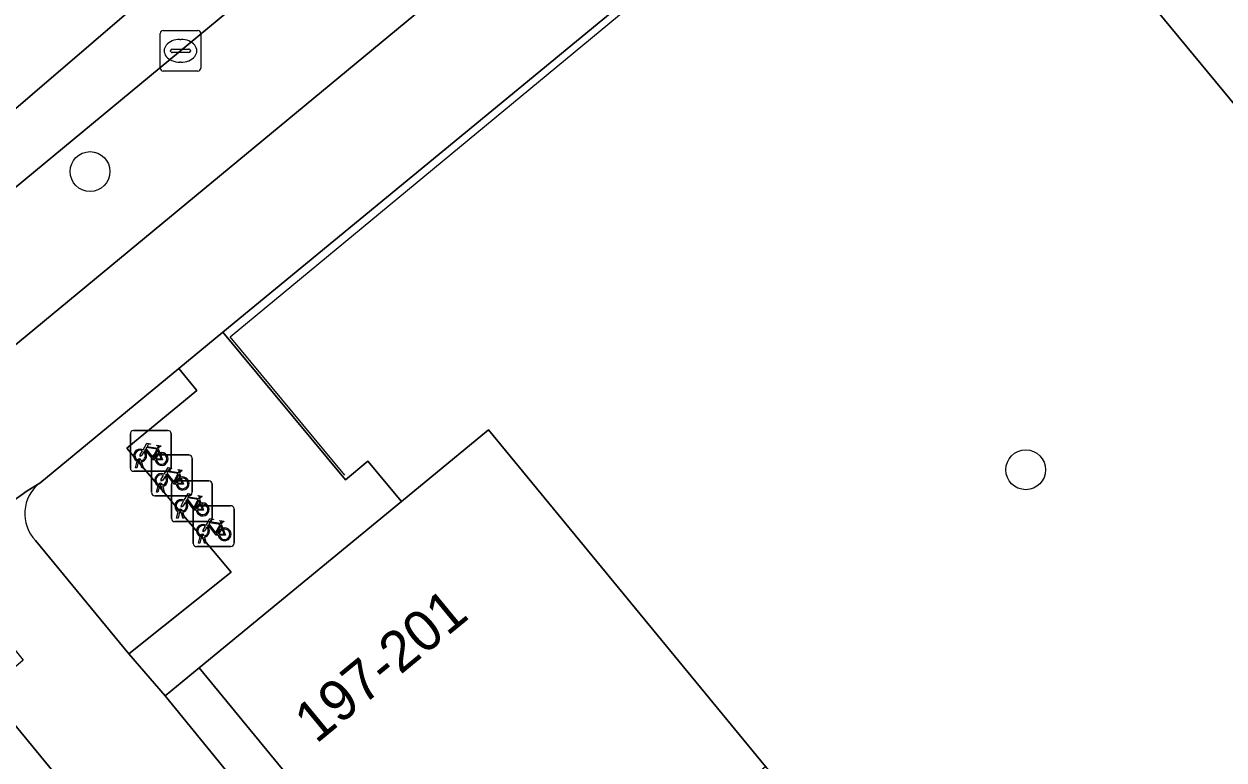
# Model space of a CAD drawing. Extents: x 162344 to 162869, y 381217 to 381818.
# Drawn here: x 162429.6 to 162459.05, y 381714.88 to 381732.95 of the extents above; entities that cross this region are included whole.
import ezdxf

# ---------------------------------------------------------------- set-up
doc = ezdxf.new("R2010")
doc.units = 0
for name, color, linetype in [('IMGEO_Berm_groen', 7, 'Continuous'), ('IMGEO_Boom', 7, 'Continuous'), ('IMGEO_Fietsenrek', 7, 'Continuous'), ('IMGEO_Fietspad_open', 7, 'Continuous'), ('IMGEO_Groenvoorziening', 7, 'Continuous'), ('IMGEO_Hek', 7, 'Continuous'), ('IMGEO_Kolk', 7, 'Continuous'), ('IMGEO_Pand', 7, 'Continuous'), ('IMGEO_Pand_nummerreeks', 7, 'Continuous'), ('IMGEO_Parkeervlak_open', 7, 'Continuous'), ('IMGEO_Rijbaan_lokaal_open', 7, 'Continuous'), ('IMGEO_Voetpad_open', 7, 'Continuous')]:
    doc.layers.add(name, color=color, linetype=linetype)

msp = doc.modelspace()

# ---------------------------------------------------------------- linework, layer by layer
at = {"layer": 'IMGEO_Berm_groen'}
msp.add_lwpolyline([(162485.569, 381771.54), (162486.346, 381772.165), (162499.033, 381781.642), (162500.475, 381782.734), (162498.716, 381785.09), (162498.222, 381784.754), (162492.604, 381780.797), (162491.487, 381780.055), (162488.724, 381777.94), (162487.946, 381777.388), (162484.993, 381774.972), (162478.211, 381769.449), (162471.4, 381763.826), (162457.878, 381752.522), (162455.794, 381750.801), (162451.521, 381747.272), (162447.905, 381744.275), (162433.442, 381732.29), (162428.876, 381728.513), (162426.389, 381726.442), (162426.314, 381726.37), (162428.207, 381724.094), (162451.823, 381743.637), (162459.348, 381749.88)], close=True, dxfattribs=at)
at = {"layer": 'IMGEO_Boom'}
for centre in [(162431.222, 381729.325), (162454.185, 381722.001)]:
    msp.add_circle(centre, 0.489, dxfattribs=at)
at = {"layer": 'IMGEO_Fietsenrek'}
for p, q in [((162432.286, 381722.966), (162433.127, 381722.966)), ((162433.127, 381722.966), (162432.286, 381722.966)), ((162432.211, 381722.041), (162432.211, 381722.882)), ((162432.211, 381722.882), (162432.211, 381722.041)), ((162433.211, 381722.891), (162433.211, 381722.05)), ((162433.211, 381722.05), (162433.211, 381722.891)), ((162432.803, 381722.365), (162433.644, 381722.365)), ((162433.644, 381722.365), (162432.803, 381722.365)), ((162432.898, 381722.515), (162432.934, 381722.42)), ((162432.338, 381722.05), (162432.377, 381722.21)), ((162432.372, 381722.05), (162432.338, 381722.05)), ((162432.407, 381722.198), (162432.372, 381722.05)), ((162432.449, 381722.222), (162432.448, 381722.226)), ((162432.49, 381722.05), (162432.456, 381722.192)), ((162432.48, 381722.233), (162432.481, 381722.226)), ((162432.488, 381722.196), (162432.523, 381722.05)), ((162432.523, 381722.05), (162432.49, 381722.05)), ((162432.728, 381721.44), (162432.728, 381722.281)), ((162432.728, 381722.281), (162432.728, 381721.44)), ((162433.728, 381722.29), (162433.728, 381721.449)), ((162433.728, 381721.449), (162433.728, 381722.29)), ((162433.136, 381721.966), (162432.295, 381721.966)), ((162432.295, 381721.966), (162433.136, 381721.966)), ((162433.295, 381721.728), (162434.136, 381721.728)), ((162434.136, 381721.728), (162433.295, 381721.728)), ((162433.415, 381721.914), (162433.451, 381721.819)), ((162432.855, 381721.449), (162432.894, 381721.609)), ((162432.889, 381721.449), (162432.855, 381721.449)), ((162432.924, 381721.597), (162432.889, 381721.449)), ((162432.966, 381721.621), (162432.965, 381721.625)), ((162433.007, 381721.449), (162432.973, 381721.591)), ((162432.997, 381721.632), (162432.998, 381721.625)), ((162433.005, 381721.595), (162433.04, 381721.449)), ((162433.04, 381721.449), (162433.007, 381721.449)), ((162433.22, 381720.803), (162433.22, 381721.644)), ((162433.22, 381721.644), (162433.22, 381720.803)), ((162434.22, 381721.653), (162434.22, 381720.812)), ((162434.22, 381720.812), (162434.22, 381721.653)), ((162433.653, 381721.365), (162432.812, 381721.365)), ((162432.812, 381721.365), (162433.653, 381721.365)), ((162433.907, 381721.277), (162433.943, 381721.182)), ((162433.347, 381720.812), (162433.386, 381720.972)), ((162433.416, 381720.96), (162433.381, 381720.812)), ((162433.458, 381720.984), (162433.457, 381720.988)), ((162433.499, 381720.812), (162433.465, 381720.954)), ((162433.489, 381720.995), (162433.49, 381720.988)), ((162433.497, 381720.958), (162433.532, 381720.812)), ((162433.756, 381720.192), (162433.756, 381721.033)), ((162433.756, 381721.033), (162433.756, 381720.192)), ((162433.831, 381721.117), (162434.672, 381721.117)), ((162434.672, 381721.117), (162433.831, 381721.117)), ((162434.756, 381721.042), (162434.756, 381720.201)), ((162434.756, 381720.201), (162434.756, 381721.042)), ((162434.145, 381720.728), (162433.304, 381720.728)), ((162433.304, 381720.728), (162434.145, 381720.728)), ((162433.381, 381720.812), (162433.347, 381720.812)), ((162433.532, 381720.812), (162433.499, 381720.812)), ((162434.443, 381720.666), (162434.479, 381720.571)), ((162433.883, 381720.201), (162433.922, 381720.361)), ((162433.952, 381720.349), (162433.917, 381720.201)), ((162433.994, 381720.373), (162433.993, 381720.377)), ((162434.035, 381720.201), (162434.001, 381720.343)), ((162434.025, 381720.384), (162434.026, 381720.377)), ((162434.033, 381720.347), (162434.068, 381720.201)), ((162434.681, 381720.117), (162433.84, 381720.117)), ((162433.84, 381720.117), (162434.681, 381720.117)), ((162433.917, 381720.201), (162433.883, 381720.201)), ((162434.068, 381720.201), (162434.035, 381720.201))]:
    msp.add_line(p, q, dxfattribs=at)
for points in [[(162432.524, 381722.492), (162432.619, 381722.656), (162432.705, 381722.642), (162432.707, 381722.633), (162432.651, 381722.622), (162432.624, 381722.577), (162432.88, 381722.536)], [(162432.88, 381722.536), (162432.905, 381722.585), (162432.899, 381722.589), (162432.876, 381722.593), (162432.864, 381722.6), (162432.863, 381722.603), (162432.865, 381722.608), (162432.96, 381722.593), (162432.962, 381722.583), (162432.952, 381722.57), (162432.94, 381722.564), (162432.926, 381722.57), (162432.898, 381722.515)], [(162432.545, 381722.44), (162432.493, 381722.35), (162432.453, 381722.325), (162432.454, 381722.372), (162432.509, 381722.466)], [(162432.82, 381722.248), (162432.77, 381722.248), (162432.579, 381722.499), (162432.56, 381722.467)], [(162432.867, 381722.511), (162432.61, 381722.552), (162432.593, 381722.523), (162432.76, 381722.303), (162432.867, 381722.511)], [(162432.915, 381722.413), (162432.885, 381722.49), (162432.776, 381722.272), (162432.819, 381722.272)], [(162432.849, 381722.272), (162432.969, 381722.271), (162432.925, 381722.385)], [(162432.945, 381722.392), (162433, 381722.247), (162432.85, 381722.247)], [(162433.041, 381721.891), (162433.136, 381722.055), (162433.222, 381722.041), (162433.224, 381722.032), (162433.168, 381722.021), (162433.141, 381721.976), (162433.397, 381721.935)], [(162433.062, 381721.839), (162433.01, 381721.749), (162432.97, 381721.724), (162432.971, 381721.771), (162433.026, 381721.865)], [(162433.337, 381721.647), (162433.287, 381721.647), (162433.096, 381721.898), (162433.077, 381721.866)], [(162433.384, 381721.91), (162433.127, 381721.951), (162433.11, 381721.922), (162433.277, 381721.702), (162433.384, 381721.91)], [(162433.432, 381721.812), (162433.402, 381721.889), (162433.293, 381721.671), (162433.336, 381721.671)], [(162433.366, 381721.671), (162433.486, 381721.67), (162433.442, 381721.784)], [(162433.462, 381721.791), (162433.517, 381721.646), (162433.367, 381721.646)], [(162433.397, 381721.935), (162433.422, 381721.984), (162433.416, 381721.988), (162433.393, 381721.992), (162433.381, 381721.999), (162433.38, 381722.002), (162433.382, 381722.007), (162433.477, 381721.992), (162433.479, 381721.982), (162433.469, 381721.969), (162433.457, 381721.963), (162433.443, 381721.969), (162433.415, 381721.914)], [(162433.554, 381721.202), (162433.502, 381721.112), (162433.462, 381721.087), (162433.463, 381721.134), (162433.518, 381721.228)], [(162433.533, 381721.254), (162433.628, 381721.418), (162433.714, 381721.404), (162433.716, 381721.395), (162433.66, 381721.384), (162433.633, 381721.339), (162433.889, 381721.298)], [(162433.829, 381721.01), (162433.779, 381721.01), (162433.588, 381721.261), (162433.569, 381721.229)], [(162433.876, 381721.273), (162433.619, 381721.314), (162433.602, 381721.285), (162433.769, 381721.065), (162433.876, 381721.273)], [(162433.924, 381721.175), (162433.894, 381721.252), (162433.785, 381721.034), (162433.828, 381721.034)], [(162433.858, 381721.034), (162433.978, 381721.033), (162433.934, 381721.147)], [(162433.954, 381721.154), (162434.009, 381721.009), (162433.859, 381721.009)], [(162433.889, 381721.298), (162433.914, 381721.347), (162433.908, 381721.351), (162433.885, 381721.355), (162433.873, 381721.362), (162433.872, 381721.365), (162433.874, 381721.37), (162433.969, 381721.355), (162433.971, 381721.345), (162433.961, 381721.332), (162433.949, 381721.326), (162433.935, 381721.332), (162433.907, 381721.277)], [(162434.09, 381720.591), (162434.038, 381720.501), (162433.998, 381720.476), (162433.999, 381720.523), (162434.054, 381720.617)], [(162434.069, 381720.643), (162434.164, 381720.807), (162434.25, 381720.793), (162434.252, 381720.784), (162434.196, 381720.773), (162434.169, 381720.728), (162434.425, 381720.687)], [(162434.365, 381720.399), (162434.315, 381720.399), (162434.124, 381720.65), (162434.105, 381720.618)], [(162434.412, 381720.662), (162434.155, 381720.703), (162434.138, 381720.674), (162434.305, 381720.454), (162434.412, 381720.662)], [(162434.46, 381720.564), (162434.43, 381720.641), (162434.321, 381720.423), (162434.364, 381720.423)], [(162434.49, 381720.543), (162434.545, 381720.398), (162434.395, 381720.398)], [(162434.425, 381720.687), (162434.45, 381720.736), (162434.444, 381720.74), (162434.421, 381720.744), (162434.409, 381720.751), (162434.408, 381720.754), (162434.41, 381720.759), (162434.505, 381720.744), (162434.507, 381720.734), (162434.497, 381720.721), (162434.485, 381720.715), (162434.471, 381720.721), (162434.443, 381720.666)], [(162434.394, 381720.423), (162434.514, 381720.422), (162434.47, 381720.536)]]:
    msp.add_lwpolyline(points, dxfattribs=at)
for centre, radius, start, end in [((162432.289, 381722.888), 0.0779, 92.4484, 184.2845), ((162432.289, 381722.888), 0.0779, 92.4484, 184.2845), ((162433.133, 381722.888), 0.0779, 2.4484, 94.2845), ((162433.133, 381722.888), 0.0779, 2.4484, 94.2845), ((162432.451, 381722.351), 0.159, 62.6766, 242.1369), ((162432.451, 381722.351), 0.129, 63.3192, 238.903), ((162432.451, 381722.351), 0.129, 283.6043, 43.4302), ((162432.451, 381722.351), 0.159, 283.5766, 46.6042), ((162432.806, 381722.287), 0.0779, 92.4484, 184.2845), ((162432.806, 381722.287), 0.0779, 92.4484, 184.2845), ((162432.978, 381722.267), 0.159, 113.3408, 178.3217), ((162432.978, 381722.267), 0.159, 187.0065, 105.7708), ((162432.978, 381722.267), 0.129, 113.923, 177.9556), ((162432.978, 381722.267), 0.129, 188.6715, 104.5883), ((162433.65, 381722.287), 0.0779, 2.4484, 94.2845), ((162433.65, 381722.287), 0.0779, 2.4484, 94.2845), ((162432.289, 381722.044), 0.0779, 182.4484, 274.2845), ((162432.289, 381722.044), 0.0779, 182.4484, 274.2845), ((162432.431, 381722.222), 0.0499, 12.8025, 158.6934), ((162432.451, 381722.351), 0.159, 253.9967, 271.7867), ((162432.431, 381722.222), 0.0174, 12.8025, 163.4502), ((162432.451, 381722.351), 0.129, 253.415, 269.0204), ((162433.133, 381722.044), 0.0779, 272.4484, 4.2845), ((162433.133, 381722.044), 0.0779, 272.4484, 4.2845), ((162432.968, 381721.75), 0.159, 62.6766, 242.1369), ((162432.968, 381721.75), 0.129, 63.3192, 238.903), ((162432.968, 381721.75), 0.129, 283.6043, 43.4302), ((162432.968, 381721.75), 0.159, 283.5766, 46.6042), ((162433.298, 381721.65), 0.0779, 92.4484, 184.2845), ((162433.298, 381721.65), 0.0779, 92.4484, 184.2845), ((162433.495, 381721.666), 0.159, 113.3408, 178.3217), ((162433.495, 381721.666), 0.159, 187.0065, 105.7708), ((162433.495, 381721.666), 0.129, 113.923, 177.9556), ((162433.495, 381721.666), 0.129, 188.6715, 104.5883), ((162434.142, 381721.65), 0.0779, 2.4484, 94.2845), ((162434.142, 381721.65), 0.0779, 2.4484, 94.2845), ((162432.806, 381721.443), 0.0779, 182.4484, 274.2845), ((162432.806, 381721.443), 0.0779, 182.4484, 274.2845), ((162432.948, 381721.621), 0.0499, 12.8025, 158.6934), ((162432.968, 381721.75), 0.159, 253.9967, 271.7867), ((162432.948, 381721.621), 0.0174, 12.8025, 163.4502), ((162432.968, 381721.75), 0.129, 253.415, 269.0204), ((162433.65, 381721.443), 0.0779, 272.4484, 4.2845), ((162433.65, 381721.443), 0.0779, 272.4484, 4.2845), ((162433.46, 381721.113), 0.159, 62.6766, 242.1369), ((162433.46, 381721.113), 0.129, 63.3192, 238.903), ((162433.46, 381721.113), 0.129, 283.6043, 43.4302), ((162433.46, 381721.113), 0.159, 283.5766, 46.6042), ((162433.987, 381721.029), 0.159, 113.3408, 178.3217), ((162433.987, 381721.029), 0.159, 187.0065, 105.7708), ((162433.987, 381721.029), 0.129, 113.923, 177.9556), ((162433.987, 381721.029), 0.129, 188.6715, 104.5883), ((162433.44, 381720.984), 0.0499, 12.8025, 158.6934), ((162433.46, 381721.113), 0.159, 253.9967, 271.7867), ((162433.44, 381720.984), 0.0174, 12.8025, 163.4502), ((162433.46, 381721.113), 0.129, 253.415, 269.0204), ((162433.834, 381721.039), 0.0779, 92.4484, 184.2845), ((162433.834, 381721.039), 0.0779, 92.4484, 184.2845), ((162434.678, 381721.039), 0.0779, 2.4484, 94.2845), ((162434.678, 381721.039), 0.0779, 2.4484, 94.2845), ((162433.298, 381720.806), 0.0779, 182.4484, 274.2845), ((162433.298, 381720.806), 0.0779, 182.4484, 274.2845), ((162433.996, 381720.502), 0.159, 62.6766, 242.1369), ((162433.996, 381720.502), 0.129, 63.3192, 238.903), ((162433.996, 381720.502), 0.129, 283.6043, 43.4302), ((162433.996, 381720.502), 0.159, 283.5766, 46.6042), ((162434.142, 381720.806), 0.0779, 272.4484, 4.2845), ((162434.142, 381720.806), 0.0779, 272.4484, 4.2845), ((162434.523, 381720.418), 0.159, 113.3408, 178.3217), ((162434.523, 381720.418), 0.159, 187.0065, 105.7708), ((162434.523, 381720.418), 0.129, 188.6715, 104.5883), ((162433.976, 381720.373), 0.0499, 12.8025, 158.6934), ((162433.996, 381720.502), 0.159, 253.9967, 271.7867), ((162433.976, 381720.373), 0.0174, 12.8025, 163.4502), ((162433.996, 381720.502), 0.129, 253.415, 269.0204), ((162434.523, 381720.418), 0.129, 113.923, 177.9556), ((162433.834, 381720.195), 0.0779, 182.4484, 274.2845), ((162433.834, 381720.195), 0.0779, 182.4484, 274.2845), ((162434.678, 381720.195), 0.0779, 272.4484, 4.2845), ((162434.678, 381720.195), 0.0779, 272.4484, 4.2845)]:
    msp.add_arc(centre, radius, start, end, dxfattribs=at)
at = {"layer": 'IMGEO_Fietspad_open'}
msp.add_lwpolyline([(162451.521, 381747.272), (162455.794, 381750.801), (162453.794, 381753.188), (162450.654, 381749.123), (162425.365, 381727.418), (162426.277, 381726.338), (162426.314, 381726.37), (162426.389, 381726.442), (162428.876, 381728.513), (162433.442, 381732.29), (162447.905, 381744.275)], close=True, dxfattribs=at)
at = {"layer": 'IMGEO_Groenvoorziening'}
for points in [[(162471.549, 381716.061), (162469.643, 381714.467), (162467.863, 381716.602), (162469.783, 381718.202), (162463.314, 381726.102), (162461.333, 381724.518), (162459.563, 381726.678), (162461.541, 381728.274), (162451.996, 381739.827), (162449.119, 381737.441), (162434.479, 381725.379), (162437.492, 381721.752), (162438.041, 381722.212), (162438.864, 381721.224), (162441.001, 381722.982), (162447.798, 381714.718), (162454.595, 381706.454), (162461.391, 381698.19), (162468.188, 381689.926), (162474.743, 381681.955)], [(162432.125, 381722.533), (162433.847, 381723.951), (162433.402, 381724.491), (162431.674, 381723.068), (162429.986, 381721.677)], [(162429.884, 381720.266), (162432.171, 381717.481), (162434.689, 381719.491), (162432.125, 381722.533)]]:
    msp.add_lwpolyline(points, dxfattribs=at)
msp.add_lwpolyline([(162433.897, 381717.139), (162433.063, 381716.452), (162439.822, 381708.158), (162440.694, 381708.875)], close=True, dxfattribs=at)
msp.add_arc((162430.577, 381720.925), 0.957, 128.1807, 223.55, dxfattribs=at)
at = {"layer": 'IMGEO_Hek'}
msp.add_lwpolyline([(162437.475, 381721.871), (162434.659, 381725.263), (162451.967, 381739.596), (162455.968, 381734.665)], dxfattribs=at)
at = {"layer": 'IMGEO_Kolk'}
for p, q in [((162432.941, 381731.864), (162432.941, 381732.716)), ((162433.016, 381732.79), (162433.868, 381732.79)), ((162433.942, 381732.716), (162433.942, 381731.864)), ((162433.243, 381732.333), (162433.641, 381732.333)), ((162433.429, 381732.57), (162433.454, 381732.57)), ((162433.2, 381732.284), (162433.2, 381732.296)), ((162433.638, 381732.247), (162433.24, 381732.247)), ((162433.684, 381732.296), (162433.684, 381732.284)), ((162433.868, 381731.79), (162433.016, 381731.79)), ((162433.452, 381732.01), (162433.427, 381732.01))]:
    msp.add_line(p, q, dxfattribs=at)
for points in [[(162432.941, 381731.864), (162432.941, 381732.716)], [(162433.016, 381732.79), (162433.868, 381732.79)], [(162433.942, 381732.716), (162433.942, 381731.864)], [(162433.868, 381731.79), (162433.016, 381731.79)]]:
    msp.add_lwpolyline(points, dxfattribs=at)
for centre, radius, start, end in [((162433.018, 381732.714), 0.0765, 91.552, 178.448), ((162433.018, 381732.714), 0.0765, 91.552, 178.448), ((162433.866, 381732.714), 0.0765, 1.552, 88.448), ((162433.866, 381732.714), 0.0765, 1.552, 88.448), ((162433.24, 381732.293), 0.0403, 85.8775, 175.7526), ((162433.645, 381732.295), 0.0386, 1.7309, 96.639), ((162433.237, 381732.283), 0.0366, 178.938, 274.7102), ((162433.641, 381732.29), 0.043, 264.8664, 352.4533), ((162433.018, 381731.866), 0.0765, 181.552, 268.448), ((162433.018, 381731.866), 0.0765, 181.552, 268.448), ((162433.866, 381731.866), 0.0765, 271.552, 358.448), ((162433.866, 381731.866), 0.0765, 271.552, 358.448)]:
    msp.add_arc(centre, radius, start, end, dxfattribs=at)
for centre, major_axis, ratio, start_param, end_param in [((162433.428, 381732.29), (-0.387, 0.002), 0.722429, 4.712389, 7.853982), ((162433.453, 381732.29), (-0.39, 0.002), 0.717154, 1.570796, 4.712389)]:
    msp.add_ellipse(centre, major_axis=major_axis, ratio=ratio, start_param=start_param, end_param=end_param, dxfattribs=at)
at = {"layer": 'IMGEO_Pand'}
msp.add_lwpolyline([(162447.798, 381714.718), (162441.001, 381722.982), (162438.864, 381721.224), (162433.897, 381717.139), (162440.694, 381708.875)], close=True, dxfattribs=at)
at = {"layer": 'IMGEO_Parkeervlak_open'}
msp.add_lwpolyline([(162443.923, 381698.02), (162443.858, 381698.099), (162428.688, 381716.567)], dxfattribs=at)
at = {"layer": 'IMGEO_Rijbaan_lokaal_open'}
msp.add_lwpolyline([(162444.009, 381746.21), (162425.507, 381730.862), (162423.709, 381729.379), (162425.365, 381727.418), (162450.654, 381749.123), (162453.794, 381753.188)], dxfattribs=at)
at = {"layer": 'IMGEO_Voetpad_open'}
for points in [[(162516.423, 381797.237), (162499.898, 381785.893), (162498.927, 381785.234), (162498.716, 381785.09), (162500.475, 381782.734), (162499.033, 381781.642), (162486.346, 381772.165), (162485.569, 381771.54), (162459.348, 381749.88), (162451.823, 381743.637), (162428.207, 381724.094), (162426.314, 381726.37), (162426.277, 381726.338), (162424.054, 381724.411)], [(162424.437, 381718.682), (162424.917, 381718.008), (162425.009, 381717.878), (162427.504, 381719.918), (162429.68, 381721.488), (162429.986, 381721.677), (162431.674, 381723.068), (162433.402, 381724.491), (162434.479, 381725.379), (162449.119, 381737.441), (162451.996, 381739.827), (162454.645, 381742.024), (162457.296, 381744.222), (162458.802, 381745.471), (162460.058, 381746.513), (162477.365, 381760.866)], [(162429.986, 381721.677), (162429.68, 381721.488), (162427.504, 381719.918), (162429.582, 381717.324), (162428.688, 381716.567), (162443.858, 381698.099), (162444.783, 381698.896), (162447.02, 381696.173), (162445.364, 381694.832), (162444.534, 381694.123), (162445.318, 381693.193), (162446.171, 381693.919), (162447.758, 381695.241), (162450.589, 381691.804), (162450.623, 381691.763), (162450.093, 381691.327), (162449.697, 381691), (162454.017, 381685.708)], [(162439.822, 381708.158), (162433.063, 381716.452), (162432.172, 381717.479), (162432.171, 381717.481), (162429.884, 381720.266)]]:
    msp.add_lwpolyline(points, dxfattribs=at)
for points in [[(162474.375, 381717.99), (162472.137, 381720.694), (162467.553, 381726.234), (162465.316, 381728.939), (162458.388, 381737.311), (162457.62, 381738.466), (162454.645, 381742.024), (162451.996, 381739.827), (162461.541, 381728.274), (162463.314, 381726.102), (162469.783, 381718.202), (162471.549, 381716.061), (162476.506, 381710.061), (162478.262, 381707.898), (162483.232, 381701.86), (162484.979, 381699.692), (162489.486, 381694.198), (162492.218, 381696.426), (162488.017, 381701.503), (162485.78, 381704.207), (162481.196, 381709.747), (162478.958, 381712.451)], [(162438.864, 381721.224), (162438.041, 381722.212), (162437.492, 381721.752), (162434.479, 381725.379), (162433.402, 381724.491), (162433.847, 381723.951), (162432.125, 381722.533), (162434.689, 381719.491), (162432.171, 381717.481), (162432.172, 381717.479), (162433.063, 381716.452), (162433.897, 381717.139)]]:
    msp.add_lwpolyline(points, close=True, dxfattribs=at)
msp.add_arc((162430.577, 381720.925), 0.957, 128.1807, 223.55, dxfattribs=at)

# ---------------------------------------------------------------- texts
at = {"layer": 'IMGEO_Pand_nummerreeks'}
msp.add_text('197-201', height=1, rotation=39.4371, dxfattribs=at).set_placement((162436.771, 381715.257))

doc.saveas('drawing.dxf')
